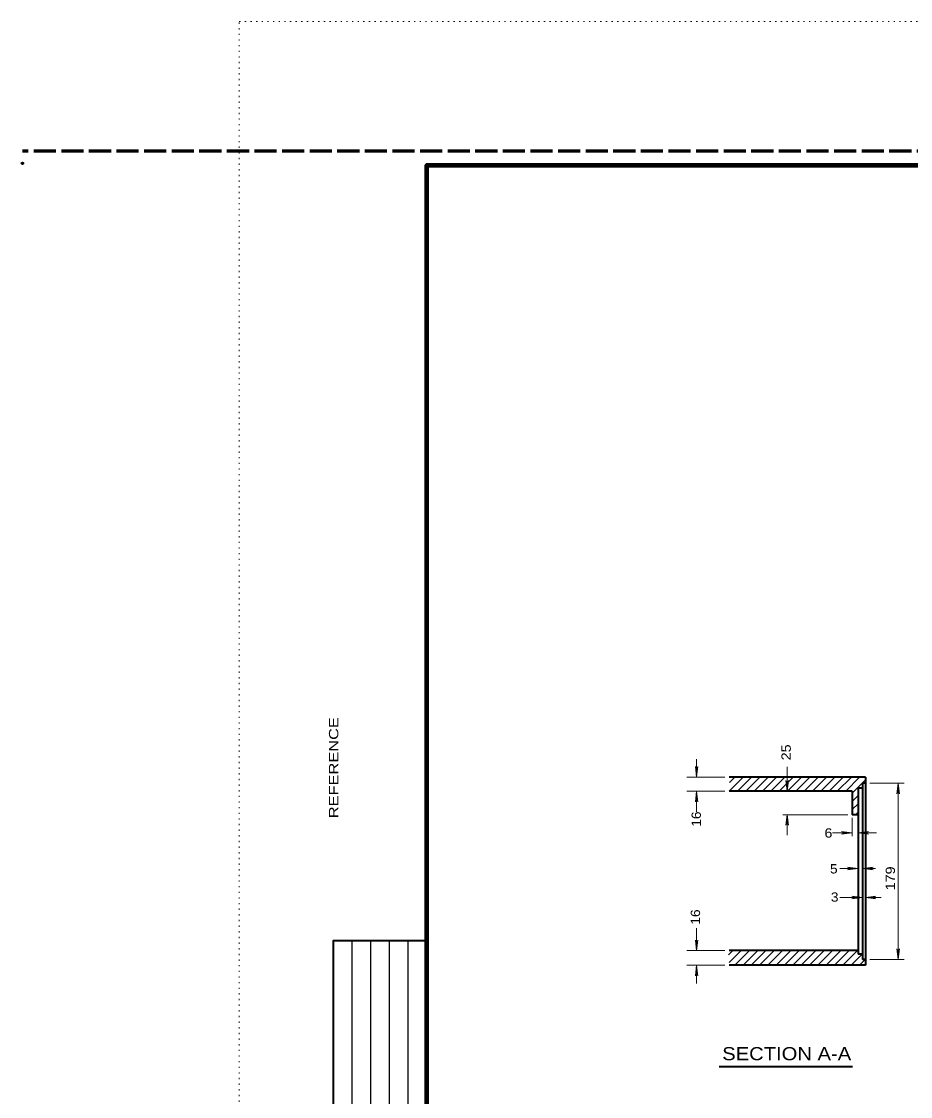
# Model space of a CAD drawing. Extents: x 312583 to 312854, y 144419 to 144597.
# Drawn here: x 312583.5 to 312655.9, y 144509.2 to 144596.8 of the extents above; entities that cross this region are included whole.
import ezdxf
from ezdxf.enums import TextEntityAlignment as Align

# ---------------------------------------------------------------- set-up
doc = ezdxf.new("R2010")
doc.units = 0
doc.header["$LTSCALE"] = 0.3
doc.header["$PDMODE"] = 32
doc.header["$PDSIZE"] = 0.15
doc.linetypes.add('DOTTED', pattern=[1.5, 0.3, -1.2])
doc.linetypes.add('LONG_DASHED', pattern=[7.5, 6, -1.5])
for name, color, linetype, lineweight in [('1', 7, 'Continuous', 40), ('2', 7, 'Continuous', 13), ('63', 7, 'DOTTED', 13)]:
    doc.layers.add(name, color=color, linetype=linetype, lineweight=lineweight)

msp = doc.modelspace()

# ---------------------------------------------------------------- linework, layer by layer
at = {"layer": '1', "linetype": 'DOTTED', "lineweight": 13}
msp.add_line((312601.2, 144418.5846), (312601.2, 144596.7846), dxfattribs=at)
at = {"layer": '1', "linetype": 'LONG_DASHED', "lineweight": 60}
msp.add_line((312851.75, 144586.2246), (312583.526, 144586.2246), dxfattribs=at)
at = {"layer": '1'}
for p, q in [((312652.2493, 144535.2006), (312641.148, 144535.2006)), ((312652.2493, 144534.7176), (312652.0116, 144534.7176)), ((312652.0116, 144534.7176), (312652.0116, 144520.3426)), ((312652.2493, 144535.2006), (312652.2493, 144519.8673)), ((312651.1683, 144534.0583), (312641.148, 144534.0583)), ((312651.1683, 144534.0583), (312651.1683, 144532.1416)), ((312652.0116, 144534.296), (312651.6513, 144534.296)), ((312651.6513, 144534.296), (312651.6513, 144520.7643)), ((312651.6513, 144532.1416), (312651.1683, 144532.1416)), ((312651.6513, 144521.0633), (312641.148, 144521.0633)), ((312652.0116, 144520.7643), (312651.6513, 144520.7643)), ((312652.2493, 144519.8673), (312641.148, 144519.8673)), ((312652.2493, 144520.3426), (312652.0116, 144520.3426))]:
    msp.add_line(p, q, dxfattribs=at)
at = {"layer": '1', "lineweight": 25}
for p, q in [((312610.4087, 144490.6573), (312610.4087, 144521.8756)), ((312611.9315, 144490.6573), (312611.9315, 144521.8756)), ((312613.4543, 144490.6573), (312613.4543, 144521.8756)), ((312614.9772, 144490.6573), (312614.9772, 144521.8756))]:
    msp.add_line(p, q, dxfattribs=at)
at = {"layer": '1', "lineweight": 158}
msp.add_lwpolyline([(312616.5, 144423.1446), (312616.5, 144585.0846), (312849, 144585.0846)], dxfattribs=at)
at = {"layer": '1', "lineweight": 35}
msp.add_lwpolyline([(312616.5, 144490.6573), (312608.8858, 144490.6573), (312608.8858, 144521.8756), (312616.5, 144521.8756)], dxfattribs=at)
at = {"layer": '1'}
msp.add_point((312583.526, 144585.2246), dxfattribs=at)
at = {"layer": '2'}
for p, q in [((312638.4953, 144535.2006), (312638.4953, 144536.6803)), ((312638.388, 144536.067), (312638.4953, 144535.791)), ((312638.4953, 144535.2006), (312638.388, 144536.067)), ((312638.6026, 144536.067), (312638.4953, 144535.791)), ((312638.4953, 144535.2006), (312638.6026, 144536.067)), ((312645.863, 144534.0583), (312645.863, 144536.0363)), ((312640.78, 144535.2006), (312637.6826, 144535.2006)), ((312645.7556, 144534.9246), (312645.863, 144534.6486)), ((312645.863, 144534.0583), (312645.7556, 144534.9246)), ((312645.9703, 144534.9246), (312645.863, 144534.6486)), ((312645.863, 144534.0583), (312645.9703, 144534.9246)), ((312652.602, 144534.7176), (312655.4156, 144534.7176)), ((312654.9326, 144534.7176), (312654.8253, 144533.8513)), ((312654.9326, 144520.3426), (312654.9326, 144534.7176)), ((312654.9326, 144534.7176), (312655.04, 144533.8513)), ((312640.78, 144534.0583), (312637.6826, 144534.0583)), ((312638.4953, 144534.0583), (312638.388, 144533.192)), ((312638.4953, 144532.3793), (312638.4953, 144534.0583)), ((312638.4953, 144534.0583), (312638.6026, 144533.192)), ((312654.8253, 144533.8513), (312654.9326, 144534.1273)), ((312655.04, 144533.8513), (312654.9326, 144534.1273)), ((312638.388, 144533.192), (312638.4953, 144533.468)), ((312638.6026, 144533.192), (312638.4953, 144533.468)), ((312650.808, 144532.1416), (312645.518, 144532.1416)), ((312645.863, 144532.1416), (312645.7556, 144531.2753)), ((312645.863, 144530.4856), (312645.863, 144532.1416)), ((312645.863, 144532.1416), (312645.9703, 144531.2753)), ((312645.7556, 144531.2753), (312645.863, 144531.5513)), ((312645.9703, 144531.2753), (312645.863, 144531.5513)), ((312651.1683, 144531.881), (312651.1683, 144530.386)), ((312649.5665, 144530.6696), (312651.1683, 144530.6696)), ((312650.302, 144530.777), (312650.578, 144530.6696)), ((312651.1683, 144530.6696), (312650.302, 144530.777)), ((312650.302, 144530.5623), (312650.578, 144530.6696)), ((312651.1683, 144530.6696), (312650.302, 144530.5623)), ((312651.6513, 144530.6696), (312652.5176, 144530.777)), ((312651.6513, 144530.6696), (312653.1453, 144530.6696)), ((312651.6513, 144530.6696), (312652.5176, 144530.5623)), ((312652.5176, 144530.777), (312652.2416, 144530.6696)), ((312652.5176, 144530.5623), (312652.2416, 144530.6696)), ((312650.1563, 144527.7486), (312651.6513, 144527.7486)), ((312650.785, 144527.856), (312651.061, 144527.7486)), ((312651.6513, 144527.7486), (312650.785, 144527.856)), ((312650.785, 144527.6413), (312651.061, 144527.7486)), ((312651.6513, 144527.7486), (312650.785, 144527.6413)), ((312652.0116, 144527.7486), (312652.878, 144527.856)), ((312652.0116, 144527.7486), (312653.0696, 144527.7486)), ((312652.0116, 144527.7486), (312652.878, 144527.6413)), ((312652.878, 144527.856), (312652.602, 144527.7486)), ((312652.878, 144527.6413), (312652.602, 144527.7486)), ((312650.1563, 144525.395), (312652.0116, 144525.395)), ((312651.1453, 144525.5023), (312651.4213, 144525.395)), ((312652.0116, 144525.395), (312651.1453, 144525.5023)), ((312651.1453, 144525.2876), (312651.4213, 144525.395)), ((312652.0116, 144525.395), (312651.1453, 144525.2876)), ((312652.2493, 144525.395), (312653.1156, 144525.5023)), ((312652.2493, 144525.395), (312653.545, 144525.395)), ((312652.2493, 144525.395), (312653.1156, 144525.2876)), ((312653.1156, 144525.5023), (312652.8396, 144525.395)), ((312653.1156, 144525.2876), (312652.8396, 144525.395)), ((312638.4953, 144521.0633), (312638.4953, 144522.8956)), ((312638.388, 144521.9296), (312638.4953, 144521.6536)), ((312638.4953, 144521.0633), (312638.388, 144521.9296)), ((312638.6026, 144521.9296), (312638.4953, 144521.6536)), ((312638.4953, 144521.0633), (312638.6026, 144521.9296)), ((312640.78, 144521.0633), (312637.6826, 144521.0633)), ((312654.8253, 144521.209), (312654.9326, 144520.933)), ((312654.9326, 144520.3426), (312654.8253, 144521.209)), ((312655.04, 144521.209), (312654.9326, 144520.933)), ((312654.9326, 144520.3426), (312655.04, 144521.209)), ((312640.78, 144519.8673), (312637.6826, 144519.8673)), ((312638.4953, 144519.8673), (312638.388, 144519.001)), ((312638.4953, 144518.3953), (312638.4953, 144519.8673)), ((312638.4953, 144519.8673), (312638.6026, 144519.001)), ((312652.602, 144520.3426), (312655.4156, 144520.3426)), ((312638.388, 144519.001), (312638.4953, 144519.277)), ((312638.6026, 144519.001), (312638.4953, 144519.277))]:
    msp.add_line(p, q, dxfattribs=at)
at = {"layer": '2', "lineweight": 25}
for p, q in [((312641.1556, 144534.0583), (312642.298, 144535.2006)), ((312641.1863, 144534.7636), (312641.6156, 144535.2006)), ((312641.838, 144534.0583), (312642.9726, 144535.2006)), ((312642.5126, 144534.0583), (312643.655, 144535.2006)), ((312643.195, 144534.0583), (312644.3296, 144535.2006)), ((312643.8696, 144534.0583), (312645.0043, 144535.2006)), ((312644.5443, 144534.0583), (312645.6866, 144535.2006)), ((312645.2266, 144534.0583), (312646.3613, 144535.2006)), ((312645.9013, 144534.0583), (312647.0436, 144535.2006)), ((312646.576, 144534.0583), (312647.7183, 144535.2006)), ((312647.2583, 144534.0583), (312648.393, 144535.2006)), ((312647.933, 144534.0583), (312649.0753, 144535.2006)), ((312648.6153, 144534.0583), (312649.75, 144535.2006)), ((312649.29, 144534.0583), (312650.4323, 144535.2006)), ((312649.9646, 144534.0583), (312651.107, 144535.2006)), ((312650.647, 144534.0583), (312651.7816, 144535.2006)), ((312651.1683, 144533.905), (312652.2493, 144534.986)), ((312651.1683, 144533.2303), (312651.6513, 144533.7056)), ((312651.1683, 144532.5556), (312651.6513, 144533.031)), ((312651.4366, 144532.1416), (312651.6513, 144532.3563)), ((312641.4393, 144521.0633), (312641.0943, 144520.7183)), ((312641.148, 144520.0973), (312642.114, 144521.0633)), ((312641.6003, 144519.8673), (312642.7963, 144521.0633)), ((312642.275, 144519.8673), (312643.471, 144521.0633)), ((312642.9496, 144519.8673), (312644.1456, 144521.0633)), ((312643.632, 144519.8673), (312644.828, 144521.0633)), ((312644.3066, 144519.8673), (312645.5026, 144521.0633)), ((312644.989, 144519.8673), (312646.185, 144521.0633)), ((312645.6636, 144519.8673), (312646.8596, 144521.0633)), ((312646.3383, 144519.8673), (312647.5343, 144521.0633)), ((312647.0206, 144519.8673), (312648.2166, 144521.0633)), ((312647.6953, 144519.8673), (312648.8913, 144521.0633)), ((312648.3776, 144519.8673), (312649.5736, 144521.0633)), ((312649.0523, 144519.8673), (312650.2483, 144521.0633)), ((312649.727, 144519.8673), (312650.923, 144521.0633)), ((312650.4093, 144519.8673), (312651.6053, 144521.0633)), ((312651.084, 144519.8673), (312651.981, 144520.7643)), ((312651.7586, 144519.8673), (312652.2416, 144520.3426))]:
    msp.add_line(p, q, dxfattribs=at)
at = {"layer": '2', "lineweight": 35}
msp.add_line((312640.3226, 144511.6211), (312651.2008, 144511.6211), dxfattribs=at)
at = {"layer": '63'}
msp.add_line((312601.2, 144596.7846), (312853.5, 144596.7846), dxfattribs=at)

# ---------------------------------------------------------------- texts
at = {"layer": '1', "width": 1.3}
msp.add_text('REFERENCE                                                              ', height=0.7682, rotation=90, dxfattribs=at).set_placement((312609.2854, 144531.8549))
at = {"layer": '2'}
for s, width, p in [('25 ', 1.15, (312646.1696, 144536.5696)), ('16 ', 1.1, (312638.8426, 144531.1582)), ('179 ', 1.15, (312654.6656, 144525.9747)), ('16 ', 1.1, (312638.7745, 144523.1793))]:
    msp.add_text(s, height=0.76, rotation=90, dxfattribs=dict(at, width=width)).set_placement(p)
for s, width, p in [('6 ', 1.15, (312648.9147, 144530.2719)), ('5 ', 1.1, (312649.367, 144527.3509)), ('3 ', 1.1, (312649.4378, 144525.0528))]:
    msp.add_text(s, height=0.76, dxfattribs=dict(at, width=width)).set_placement(p)
at = {"layer": '2', "width": 1.15}
msp.add_text('SECTION A-A', height=1.07, dxfattribs=at).set_placement((312645.8374, 144512.1314), align=Align.CENTER)

doc.saveas('drawing.dxf')
